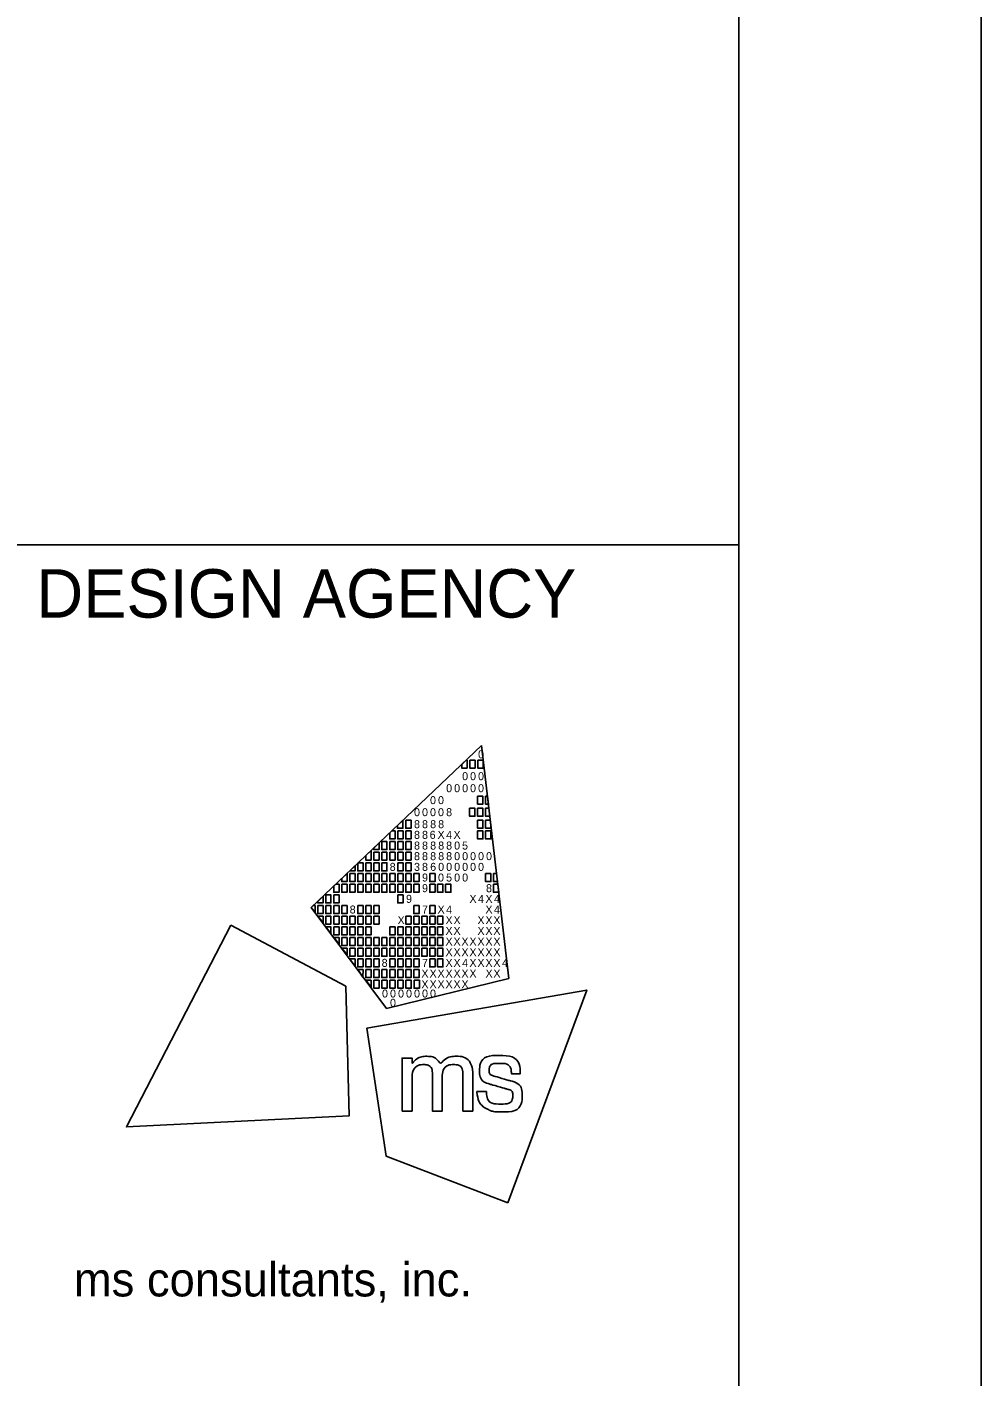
# Model space of a CAD drawing. Extents: x -5.3 to 69.2, y -33.8 to 22.
# Drawn here: x 32.03 to 34, y 2.785 to 5.569 of the extents above; entities that cross this region are included whole.
import ezdxf

# ---------------------------------------------------------------- set-up
doc = ezdxf.new("R2010")
doc.units = 0
for name, color, linetype in [('Default', 7, 'Continuous'), ('SH_Border', 7, 'Continuous'), ('SH_Cut_Line', 7, 'Continuous'), ('SH_Data', 7, 'Continuous')]:
    doc.layers.add(name, color=color, linetype=linetype)

msp = doc.modelspace()

# ---------------------------------------------------------------- linework, layer by layer
at = {"layer": 'Default'}
for p, q in [((32.6175, 3.7519), (32.9688, 4.0861)), ((32.9688, 4.0861), (32.9688, 4.0861)), ((32.9688, 4.0861), (33.0253, 3.6052)), ((32.773, 3.543), (32.6175, 3.7519)), ((33.0253, 3.6052), (32.773, 3.543))]:
    msp.add_line(p, q, dxfattribs=at)
for points in [[(32.9279, 4.0472), (32.9369, 4.0558), (32.9389, 4.0558), (32.9389, 4.0393), (32.9279, 4.0393)], [(32.9444, 4.0558), (32.9554, 4.0558), (32.9554, 4.0393), (32.9444, 4.0393)], [(32.9609, 4.0558), (32.9719, 4.0558), (32.9719, 4.0393), (32.9609, 4.0393)], [(32.9441, 3.9567), (32.9551, 3.9567), (32.9551, 3.9402), (32.9441, 3.9402)], [(32.9606, 3.9815), (32.9716, 3.9815), (32.9716, 3.965), (32.9606, 3.965)], [(32.9606, 3.9567), (32.9716, 3.9567), (32.9716, 3.9402), (32.9606, 3.9402)], [(32.9771, 3.9815), (32.9811, 3.9815), (32.983, 3.965), (32.9771, 3.965)], [(32.9771, 3.9567), (32.984, 3.9567), (32.9859, 3.9402), (32.9771, 3.9402)], [(32.7953, 3.9211), (32.8064, 3.9316), (32.8064, 3.9154), (32.7953, 3.9154)], [(32.8123, 3.9319), (32.8233, 3.9319), (32.8233, 3.9154), (32.8123, 3.9154)], [(32.9606, 3.9319), (32.9716, 3.9319), (32.9716, 3.9154), (32.9606, 3.9154)], [(32.9771, 3.9319), (32.9869, 3.9319), (32.9881, 3.9218), (32.9881, 3.9154), (32.9771, 3.9154)], [(32.7958, 3.9099), (32.8068, 3.9099), (32.8068, 3.8934), (32.7958, 3.8934)], [(32.8123, 3.9099), (32.8233, 3.9099), (32.8233, 3.8934), (32.8123, 3.8934)], [(32.9606, 3.9099), (32.9716, 3.9099), (32.9716, 3.8934), (32.9606, 3.8934)], [(32.9771, 3.9099), (32.9881, 3.9099), (32.9881, 3.8934), (32.9771, 3.8934)], [(32.7627, 3.8879), (32.7737, 3.8879), (32.7737, 3.8714), (32.7627, 3.8714)], [(32.7793, 3.8879), (32.7903, 3.8879), (32.7903, 3.8714), (32.7793, 3.8714)], [(32.7958, 3.8879), (32.8068, 3.8879), (32.8068, 3.8714), (32.7958, 3.8714)], [(32.8123, 3.8879), (32.8233, 3.8879), (32.8233, 3.8714), (32.8123, 3.8714)], [(32.7297, 3.8439), (32.7407, 3.8439), (32.7407, 3.8273), (32.7297, 3.8273)], [(32.7462, 3.8659), (32.7572, 3.8659), (32.7572, 3.8494), (32.7462, 3.8494)], [(32.7462, 3.8439), (32.7572, 3.8439), (32.7572, 3.8273), (32.7462, 3.8273)], [(32.7627, 3.8659), (32.7737, 3.8659), (32.7737, 3.8494), (32.7627, 3.8494)], [(32.7627, 3.8439), (32.7737, 3.8439), (32.7737, 3.8273), (32.7627, 3.8273)], [(32.7793, 3.8659), (32.7903, 3.8659), (32.7903, 3.8494), (32.7793, 3.8494)], [(32.7958, 3.8659), (32.8068, 3.8659), (32.8068, 3.8494), (32.7958, 3.8494)], [(32.7958, 3.8439), (32.8068, 3.8439), (32.8068, 3.8273), (32.7958, 3.8273)], [(32.8123, 3.8659), (32.8233, 3.8659), (32.8233, 3.8494), (32.8123, 3.8494)], [(32.8123, 3.8439), (32.8233, 3.8439), (32.8233, 3.8273), (32.8123, 3.8273)], [(32.6967, 3.8218), (32.7077, 3.8218), (32.7077, 3.8053), (32.6967, 3.8053)], [(32.7132, 3.8218), (32.7242, 3.8218), (32.7242, 3.8053), (32.7132, 3.8053)], [(32.7297, 3.8218), (32.7407, 3.8218), (32.7407, 3.8053), (32.7297, 3.8053)], [(32.7462, 3.8218), (32.7572, 3.8218), (32.7572, 3.8053), (32.7462, 3.8053)], [(32.7627, 3.8218), (32.7737, 3.8218), (32.7737, 3.8053), (32.7627, 3.8053)], [(32.7793, 3.8218), (32.7903, 3.8218), (32.7903, 3.8053), (32.7793, 3.8053)], [(32.7958, 3.8218), (32.8068, 3.8218), (32.8068, 3.8053), (32.7958, 3.8053)], [(32.8123, 3.8218), (32.8233, 3.8218), (32.8233, 3.8053), (32.8123, 3.8053)], [(32.8288, 3.8218), (32.8398, 3.8218), (32.8398, 3.8053), (32.8288, 3.8053)], [(32.8618, 3.8218), (32.8728, 3.8218), (32.8728, 3.8053), (32.8618, 3.8053)], [(32.9771, 3.8218), (32.9881, 3.8218), (32.9881, 3.8053), (32.9771, 3.8053)], [(32.9935, 3.8218), (32.9998, 3.8218), (33.0018, 3.8053), (32.9935, 3.8053)], [(32.6802, 3.7998), (32.6912, 3.7998), (32.6912, 3.7833), (32.6802, 3.7833)], [(32.6967, 3.7998), (32.7077, 3.7998), (32.7077, 3.7833), (32.6967, 3.7833)], [(32.7132, 3.7998), (32.7242, 3.7998), (32.7242, 3.7833), (32.7132, 3.7833)], [(32.7297, 3.7998), (32.7407, 3.7998), (32.7407, 3.7833), (32.7297, 3.7833)], [(32.7462, 3.7998), (32.7572, 3.7998), (32.7572, 3.7833), (32.7462, 3.7833)], [(32.7627, 3.7998), (32.7737, 3.7998), (32.7737, 3.7833), (32.7627, 3.7833)], [(32.7793, 3.7998), (32.7903, 3.7998), (32.7903, 3.7833), (32.7793, 3.7833)], [(32.7958, 3.7998), (32.8068, 3.7998), (32.8068, 3.7833), (32.7958, 3.7833)], [(32.8123, 3.7998), (32.8233, 3.7998), (32.8233, 3.7833), (32.8123, 3.7833)], [(32.8288, 3.7998), (32.8398, 3.7998), (32.8398, 3.7833), (32.8288, 3.7833)], [(32.8618, 3.7998), (32.8728, 3.7998), (32.8728, 3.7833), (32.8618, 3.7833)], [(32.8783, 3.7998), (32.8893, 3.7998), (32.8893, 3.7833), (32.8783, 3.7833)], [(32.8947, 3.7998), (32.9057, 3.7998), (32.9057, 3.7833), (32.8947, 3.7833)], [(32.9935, 3.7998), (33.0024, 3.7998), (33.0044, 3.7833), (32.9935, 3.7833)], [(32.6471, 3.7778), (32.6581, 3.7778), (32.6581, 3.7613), (32.6471, 3.7613)], [(32.6637, 3.7778), (32.6747, 3.7778), (32.6747, 3.7613), (32.6637, 3.7613)], [(32.7958, 3.7778), (32.8068, 3.7778), (32.8068, 3.7613), (32.7958, 3.7613)], [(32.6306, 3.7558), (32.6416, 3.7558), (32.6416, 3.7393), (32.6306, 3.7393)], [(32.6306, 3.7338), (32.6416, 3.7338), (32.6416, 3.72)], [(32.6471, 3.7558), (32.6581, 3.7558), (32.6581, 3.7393), (32.6471, 3.7393)], [(32.6471, 3.7338), (32.6581, 3.7338), (32.6581, 3.7173), (32.6471, 3.7173)], [(32.6637, 3.7558), (32.6747, 3.7558), (32.6747, 3.7393), (32.6637, 3.7393)], [(32.6637, 3.7338), (32.6747, 3.7338), (32.6747, 3.7173), (32.6637, 3.7173)], [(32.6802, 3.7558), (32.6912, 3.7558), (32.6912, 3.7393), (32.6802, 3.7393)], [(32.6802, 3.7338), (32.6912, 3.7338), (32.6912, 3.7173), (32.6802, 3.7173)], [(32.6967, 3.7338), (32.7077, 3.7338), (32.7077, 3.7173), (32.6967, 3.7173)], [(32.7132, 3.7558), (32.7242, 3.7558), (32.7242, 3.7393), (32.7132, 3.7393)], [(32.7132, 3.7338), (32.7242, 3.7338), (32.7242, 3.7173), (32.7132, 3.7173)], [(32.7297, 3.7558), (32.7407, 3.7558), (32.7407, 3.7393), (32.7297, 3.7393)], [(32.7297, 3.7338), (32.7407, 3.7338), (32.7407, 3.7173), (32.7297, 3.7173)], [(32.7462, 3.7558), (32.7572, 3.7558), (32.7572, 3.7393), (32.7462, 3.7393)], [(32.7462, 3.7338), (32.7572, 3.7338), (32.7572, 3.7173), (32.7462, 3.7173)], [(32.8123, 3.7338), (32.8233, 3.7338), (32.8233, 3.7173), (32.8123, 3.7173)], [(32.8288, 3.7558), (32.8398, 3.7558), (32.8398, 3.7393), (32.8288, 3.7393)], [(32.8288, 3.7338), (32.8398, 3.7338), (32.8398, 3.7173), (32.8288, 3.7173)], [(32.8453, 3.7338), (32.8563, 3.7338), (32.8563, 3.7173), (32.8453, 3.7173)], [(32.8618, 3.7558), (32.8728, 3.7558), (32.8728, 3.7393), (32.8618, 3.7393)], [(32.8618, 3.7338), (32.8728, 3.7338), (32.8728, 3.7173), (32.8618, 3.7173)], [(32.8783, 3.7338), (32.8893, 3.7338), (32.8893, 3.7173), (32.8783, 3.7173)], [(32.6471, 3.7117), (32.6581, 3.7117), (32.6581, 3.698)], [(32.6637, 3.7117), (32.6747, 3.7117), (32.6747, 3.6952), (32.6637, 3.6952)], [(32.6802, 3.7117), (32.6912, 3.7117), (32.6912, 3.6952), (32.6802, 3.6952)], [(32.6967, 3.7117), (32.7077, 3.7117), (32.7077, 3.6952), (32.6967, 3.6952)], [(32.7132, 3.7117), (32.7242, 3.7117), (32.7242, 3.6952), (32.7132, 3.6952)], [(32.7297, 3.7117), (32.7407, 3.7117), (32.7407, 3.6952), (32.7297, 3.6952)], [(32.7793, 3.7117), (32.7903, 3.7117), (32.7903, 3.6952), (32.7793, 3.6952)], [(32.7958, 3.7117), (32.8068, 3.7117), (32.8068, 3.6952), (32.7958, 3.6952)], [(32.8123, 3.7117), (32.8233, 3.7117), (32.8233, 3.6952), (32.8123, 3.6952)], [(32.8288, 3.7117), (32.8398, 3.7117), (32.8398, 3.6952), (32.8288, 3.6952)], [(32.8453, 3.7117), (32.8563, 3.7117), (32.8563, 3.6952), (32.8453, 3.6952)], [(32.8618, 3.7117), (32.8728, 3.7117), (32.8728, 3.6952), (32.8618, 3.6952)], [(32.8783, 3.7117), (32.8893, 3.7117), (32.8893, 3.6952), (32.8783, 3.6952)], [(32.6637, 3.6897), (32.6747, 3.6897), (32.6747, 3.676)], [(32.6747, 3.6897), (32.6747, 3.6897), (32.6747, 3.6897)], [(32.6802, 3.6897), (32.6912, 3.6897), (32.6912, 3.6732), (32.6802, 3.6732)], [(32.6967, 3.6897), (32.7077, 3.6897), (32.7077, 3.6732), (32.6967, 3.6732)], [(32.7132, 3.6897), (32.7242, 3.6897), (32.7242, 3.6732), (32.7132, 3.6732)], [(32.7297, 3.6897), (32.7407, 3.6897), (32.7407, 3.6732), (32.7297, 3.6732)], [(32.7462, 3.6897), (32.7572, 3.6897), (32.7572, 3.6732), (32.7462, 3.6732)], [(32.7627, 3.6897), (32.7737, 3.6897), (32.7737, 3.6732), (32.7627, 3.6732)], [(32.7793, 3.6897), (32.7903, 3.6897), (32.7903, 3.6732), (32.7793, 3.6732)], [(32.7958, 3.6897), (32.8068, 3.6897), (32.8068, 3.6732), (32.7958, 3.6732)], [(32.8123, 3.6897), (32.8233, 3.6897), (32.8233, 3.6732), (32.8123, 3.6732)], [(32.8288, 3.6897), (32.8398, 3.6897), (32.8398, 3.6732), (32.8288, 3.6732)], [(32.8453, 3.6897), (32.8563, 3.6897), (32.8563, 3.6732), (32.8453, 3.6732)], [(32.8618, 3.6897), (32.8728, 3.6897), (32.8728, 3.6732), (32.8618, 3.6732)], [(32.8783, 3.6897), (32.8893, 3.6897), (32.8893, 3.6732), (32.8783, 3.6732)], [(32.6802, 3.6677), (32.6912, 3.6677), (32.6912, 3.654)], [(32.6967, 3.6677), (32.7077, 3.6677), (32.7077, 3.6512), (32.6967, 3.6512)], [(32.7132, 3.6677), (32.7242, 3.6677), (32.7242, 3.6512), (32.7132, 3.6512)], [(32.7297, 3.6677), (32.7407, 3.6677), (32.7407, 3.6512), (32.7297, 3.6512)], [(32.7462, 3.6677), (32.7572, 3.6677), (32.7572, 3.6512), (32.7462, 3.6512)], [(32.7627, 3.6677), (32.7737, 3.6677), (32.7737, 3.6512), (32.7627, 3.6512)], [(32.7793, 3.6677), (32.7903, 3.6677), (32.7903, 3.6512), (32.7793, 3.6512)], [(32.7958, 3.6677), (32.8068, 3.6677), (32.8068, 3.6512), (32.7958, 3.6512)], [(32.8123, 3.6677), (32.8233, 3.6677), (32.8233, 3.6512), (32.8123, 3.6512)], [(32.8288, 3.6677), (32.8398, 3.6677), (32.8398, 3.6512), (32.8288, 3.6512)], [(32.8453, 3.6677), (32.8563, 3.6677), (32.8563, 3.6512), (32.8453, 3.6512)], [(32.8618, 3.6677), (32.8728, 3.6677), (32.8728, 3.6512), (32.8618, 3.6512)], [(32.8783, 3.6677), (32.8893, 3.6677), (32.8893, 3.6512), (32.8783, 3.6512)], [(32.7077, 3.6305), (32.6965, 3.6457), (32.7077, 3.6457)], [(32.7132, 3.6457), (32.7242, 3.6457), (32.7242, 3.6292), (32.7132, 3.6292)], [(32.724, 3.6082), (32.7132, 3.6237), (32.7242, 3.6237)], [(32.7297, 3.6457), (32.7407, 3.6457), (32.7407, 3.6292), (32.7297, 3.6292)], [(32.7297, 3.6237), (32.7407, 3.6237), (32.7407, 3.6072), (32.7297, 3.6072)], [(32.7462, 3.6457), (32.7572, 3.6457), (32.7572, 3.6292), (32.7462, 3.6292)], [(32.7462, 3.6237), (32.7572, 3.6237), (32.7572, 3.6072), (32.7462, 3.6072)], [(32.7627, 3.6237), (32.7737, 3.6237), (32.7737, 3.6072), (32.7627, 3.6072)], [(32.7793, 3.6457), (32.7903, 3.6457), (32.7903, 3.6292), (32.7793, 3.6292)], [(32.7793, 3.6237), (32.7903, 3.6237), (32.7903, 3.6072), (32.7793, 3.6072)], [(32.7958, 3.6457), (32.8068, 3.6457), (32.8068, 3.6292), (32.7958, 3.6292)], [(32.7958, 3.6237), (32.8068, 3.6237), (32.8068, 3.6072), (32.7958, 3.6072)], [(32.8123, 3.6457), (32.8233, 3.6457), (32.8233, 3.6292), (32.8123, 3.6292)], [(32.8123, 3.6237), (32.8233, 3.6237), (32.8233, 3.6072), (32.8123, 3.6072)], [(32.8288, 3.6457), (32.8398, 3.6457), (32.8398, 3.6292), (32.8288, 3.6292)], [(32.8288, 3.6237), (32.8398, 3.6237), (32.8398, 3.6072), (32.8288, 3.6072)], [(32.8618, 3.6457), (32.8728, 3.6457), (32.8728, 3.6292), (32.8618, 3.6292)], [(32.8783, 3.6457), (32.8893, 3.6457), (32.8893, 3.6292), (32.8783, 3.6292)], [(32.7302, 3.6017), (32.7407, 3.6017), (32.7408, 3.5875)], [(32.7463, 3.6017), (32.7573, 3.6017), (32.7573, 3.5852), (32.7463, 3.5852)], [(32.763, 3.6017), (32.774, 3.6017), (32.774, 3.5852), (32.763, 3.5852)], [(32.7794, 3.6017), (32.7904, 3.6017), (32.7904, 3.5852), (32.7794, 3.5852)], [(32.796, 3.6017), (32.807, 3.6017), (32.807, 3.5852), (32.796, 3.5852)], [(32.8129, 3.6017), (32.8239, 3.6017), (32.8239, 3.5851), (32.8129, 3.5851)], [(32.8296, 3.6017), (32.8406, 3.6017), (32.8406, 3.5851), (32.8296, 3.5851)]]:
    msp.add_lwpolyline(points, close=True, dxfattribs=at)
for points in [[(32.7903, 3.9099), (32.7836, 3.9099), (32.7793, 3.9058), (32.7793, 3.8934), (32.7903, 3.8934), (32.7903, 3.9099)], [(32.7572, 3.8849), (32.7462, 3.8744), (32.7462, 3.8714), (32.7572, 3.8714), (32.7572, 3.8849)], [(32.7242, 3.8439), (32.7141, 3.8439), (32.7132, 3.843), (32.7132, 3.8273), (32.7242, 3.8273), (32.7242, 3.8439)], [(32.7407, 3.8691), (32.7297, 3.8587), (32.7297, 3.8494), (32.7407, 3.8494), (32.7407, 3.8691)], [(32.6912, 3.822), (32.6802, 3.8115), (32.6802, 3.8053), (32.6912, 3.8053), (32.6912, 3.822)], [(32.7077, 3.8377), (32.6968, 3.8273), (32.7077, 3.8273), (32.7077, 3.8377)], [(32.6747, 3.7998), (32.6679, 3.7998), (32.6637, 3.7958), (32.6637, 3.7833), (32.6747, 3.7833), (32.6747, 3.7998)], [(32.6416, 3.7749), (32.6306, 3.7644), (32.6306, 3.7613), (32.6416, 3.7613), (32.6416, 3.7749)], [(32.6251, 3.7558), (32.6216, 3.7558), (32.6175, 3.7519), (32.6251, 3.7417), (32.6251, 3.7558)], [(32.4512, 3.7149), (32.2359, 3.2988), (32.6956, 3.3215), (32.6884, 3.5892), (32.4512, 3.7149)], [(33.0229, 3.1422), (33.1859, 3.5814), (32.7324, 3.5029), (32.7722, 3.2381), (33.0229, 3.1422)]]:
    msp.add_lwpolyline(points, dxfattribs=at)
for points in [[(32.8048, 3.3315), (32.8048, 3.3315), (32.8048, 3.4409), (32.8048, 3.4409), (32.8048, 3.4409), (32.8255, 3.4409), (32.8255, 3.4409), (32.8255, 3.4409), (32.8255, 3.4297), (32.8255, 3.4297), (32.8346, 3.4399), (32.8457, 3.4445), (32.8555, 3.4445), (32.8688, 3.4445), (32.8791, 3.4372), (32.8837, 3.4266), (32.8915, 3.4381), (32.905, 3.4446), (32.9166, 3.4446), (32.9325, 3.4446), (32.9451, 3.435), (32.9494, 3.4213), (32.9494, 3.4212), (32.9494, 3.4212), (32.9494, 3.4212), (32.9501, 3.419), (32.9506, 3.4172), (32.9506, 3.4071), (32.9506, 3.4071), (32.9506, 3.3314), (32.9506, 3.3314), (32.9506, 3.3314), (32.9303, 3.3314), (32.9303, 3.3314), (32.9303, 3.3314), (32.9303, 3.4048), (32.9303, 3.4048), (32.9303, 3.4201), (32.9219, 3.4274), (32.911, 3.4274), (32.8995, 3.4274), (32.8879, 3.4171), (32.8879, 3.4001), (32.8879, 3.4001), (32.8879, 3.3315), (32.8879, 3.3315), (32.8879, 3.3315), (32.8674, 3.3315), (32.8674, 3.3315), (32.8674, 3.3315), (32.8674, 3.4059), (32.8674, 3.4059), (32.8674, 3.4203), (32.8588, 3.4274), (32.8496, 3.4274), (32.8384, 3.4274), (32.8254, 3.417), (32.8254, 3.3962), (32.8254, 3.3962), (32.8254, 3.3315), (32.8254, 3.3315), (32.8254, 3.3315), (32.8048, 3.3315), (32.8048, 3.3315)], [(32.9595, 3.3709), (32.9595, 3.3709), (32.9595, 3.3717), (32.9595, 3.3717), (32.9595, 3.3717), (32.9603, 3.3717), (32.9603, 3.3717), (32.9603, 3.3717), (32.9783, 3.3717), (32.9783, 3.3717), (32.9783, 3.3717), (32.9789, 3.3717), (32.9789, 3.3717), (32.9789, 3.3717), (32.979, 3.371), (32.979, 3.371), (32.9803, 3.3554), (32.9887, 3.346), (33.009, 3.346), (33.0273, 3.346), (33.0333, 3.3554), (33.0333, 3.3631), (33.0333, 3.3732), (33.0256, 3.3758), (33.0175, 3.378), (33.0175, 3.378), (32.987, 3.3867), (32.987, 3.3867), (32.972, 3.3909), (32.9648, 3.4019), (32.9648, 3.4142), (32.9648, 3.4303), (32.9768, 3.4462), (33.0052, 3.4462), (33.0348, 3.4462), (33.0489, 3.4285), (33.0489, 3.4095), (33.0489, 3.4095), (33.0489, 3.4087), (33.0489, 3.4087), (33.0489, 3.4087), (33.0482, 3.4087), (33.0482, 3.4087), (33.0482, 3.4087), (33.0312, 3.4087), (33.0312, 3.4087), (33.0312, 3.4087), (33.0305, 3.4087), (33.0305, 3.4087), (33.0305, 3.4087), (33.0305, 3.4094), (33.0305, 3.4094), (33.0301, 3.4208), (33.0226, 3.43), (33.0056, 3.43), (32.9891, 3.43), (32.9843, 3.4218), (32.9843, 3.4157), (32.9843, 3.4108), (32.9869, 3.4059), (32.9959, 3.4033), (32.9959, 3.4033), (33.0255, 3.3948), (33.0255, 3.3948), (33.0462, 3.3889), (33.0527, 3.3777), (33.0527, 3.3639), (33.0527, 3.3462), (33.041, 3.3298), (33.0087, 3.3298), (32.9952, 3.3298), (32.9877, 3.3321), (32.9823, 3.3348), (32.969, 3.3414), (32.9609, 3.3536), (32.9595, 3.3709)]]:
    msp.add_open_spline(points, degree=3, dxfattribs=at)
at = {"layer": 'SH_Border'}
msp.add_line((32, 4.5), (33.5, 4.5), dxfattribs=at)
msp.add_lwpolyline([(1.5, 21.5), (33.5, 21.5), (33.5, 0.5), (1.5, 0.5)], close=True, dxfattribs=at)
at = {"layer": 'SH_Cut_Line'}
msp.add_lwpolyline([(0, 0), (34, 0), (34, 22), (0, 22)], close=True, dxfattribs=at)
at = {"layer": 'SH_Data'}
msp.add_line((32.75, 3.5), (32.75, 3.5), dxfattribs=at)

# ---------------------------------------------------------------- texts
at = {"layer": 'Default'}
for s, p in [('0', (32.9617, 4.0597)), ('0', (32.9288, 4.0145)), ('0', (32.9452, 4.0145)), ('0', (32.9617, 4.0145)), ('0', (32.8958, 3.9897)), ('0', (32.9123, 3.9897)), ('0', (32.9288, 3.9897)), ('0', (32.9452, 3.9897)), ('0', (32.9617, 3.9897)), ('0', (32.8295, 3.9402)), ('0', (32.846, 3.9402)), ('0', (32.8625, 3.965)), ('0', (32.8625, 3.9402)), ('0', (32.879, 3.965)), ('0', (32.879, 3.9402)), ('8', (32.8958, 3.9402)), ('8', (32.8295, 3.9154)), ('8', (32.846, 3.9154)), ('8', (32.8628, 3.9154)), ('8', (32.8793, 3.9154)), ('8', (32.8295, 3.8934)), ('8', (32.846, 3.8934)), ('6', (32.8618, 3.8934)), ('X', (32.8781, 3.8934)), ('4', (32.8958, 3.8934)), ('X', (32.911, 3.8934)), ('8', (32.8295, 3.8713)), ('8', (32.846, 3.8713)), ('8', (32.8628, 3.8713)), ('8', (32.8794, 3.8713)), ('8', (32.8958, 3.8713)), ('0', (32.9123, 3.8713)), ('5', (32.9287, 3.8713)), ('8', (32.7793, 3.8273)), ('3', (32.8295, 3.8273)), ('8', (32.8295, 3.8494)), ('8', (32.846, 3.8494)), ('8', (32.846, 3.8273)), ('8', (32.8628, 3.8494)), ('6', (32.8629, 3.8273)), ('0', (32.8793, 3.8273)), ('8', (32.8794, 3.8494)), ('8', (32.8958, 3.8494)), ('0', (32.8958, 3.8273)), ('0', (32.9123, 3.8494)), ('0', (32.9123, 3.8273)), ('0', (32.9288, 3.8494)), ('0', (32.9288, 3.8273)), ('0', (32.9452, 3.8494)), ('0', (32.9452, 3.8273)), ('0', (32.9617, 3.8494)), ('0', (32.9617, 3.8273)), ('0', (32.9782, 3.8494)), ('9', (32.846, 3.8053)), ('0', (32.879, 3.8053)), ('5', (32.8957, 3.8053)), ('0', (32.9123, 3.8053)), ('0', (32.9288, 3.8053)), ('9', (32.846, 3.7833)), ('8', (32.9781, 3.7833)), ('9', (32.813, 3.7613)), ('X', (32.9439, 3.7613)), ('4', (32.9617, 3.7613)), ('X', (32.9769, 3.7613)), ('4', (32.9946, 3.7613)), ('8', (32.6967, 3.7393)), ('X', (32.7955, 3.7173)), ('7', (32.846, 3.7393)), ('X', (32.8781, 3.7393)), ('X', (32.8945, 3.7173)), ('4', (32.8958, 3.7393)), ('X', (32.911, 3.7173)), ('X', (32.9604, 3.7173)), ('X', (32.9769, 3.7393)), ('X', (32.9769, 3.7173)), ('X', (32.9933, 3.7173)), ('4', (32.9946, 3.7393)), ('X', (32.8945, 3.6952)), ('X', (32.911, 3.6952)), ('X', (32.9604, 3.6952)), ('X', (32.9769, 3.6952)), ('X', (32.9933, 3.6952)), ('X', (32.8945, 3.6732)), ('X', (32.911, 3.6732)), ('X', (32.9274, 3.6732)), ('X', (32.9439, 3.6732)), ('X', (32.9604, 3.6732)), ('X', (32.9769, 3.6732)), ('X', (32.9933, 3.6732)), ('X', (32.8945, 3.6512)), ('X', (32.911, 3.6512)), ('X', (32.9274, 3.6512)), ('X', (32.9439, 3.6512)), ('X', (32.9604, 3.6512)), ('X', (32.9769, 3.6512)), ('X', (32.9933, 3.6512)), ('8', (32.7627, 3.6292)), ('X', (32.8447, 3.6072)), ('7', (32.846, 3.6292)), ('X', (32.8616, 3.6072)), ('X', (32.878, 3.6072)), ('X', (32.8945, 3.6292)), ('X', (32.8945, 3.6072)), ('X', (32.911, 3.6292)), ('X', (32.911, 3.6072)), ('X', (32.9274, 3.6072)), ('4', (32.9288, 3.6292)), ('X', (32.9439, 3.6292)), ('X', (32.9439, 3.6072)), ('X', (32.9604, 3.6292)), ('X', (32.9769, 3.6292)), ('X', (32.9771, 3.6072)), ('X', (32.9933, 3.6292)), ('X', (32.9933, 3.6072)), ('4', (33.0111, 3.6292)), ('X', (32.8447, 3.5851)), ('X', (32.8616, 3.5851)), ('X', (32.878, 3.5851)), ('X', (32.8945, 3.5851)), ('X', (32.911, 3.5851)), ('X', (32.9274, 3.5851)), ('0', (32.7634, 3.5659)), ('0', (32.7799, 3.5659)), ('0', (32.7965, 3.5659)), ('0', (32.813, 3.5659)), ('0', (32.8295, 3.5659)), ('0', (32.846, 3.5659)), ('0', (32.8625, 3.5659)), ('0', (32.7799, 3.5467))]:
    msp.add_text(s, height=0.0165, rotation=360, dxfattribs=at).set_placement(p)
at = {"layer": 'SH_Border'}
msp.add_text('ms consultants, inc.', height=0.07, rotation=360, dxfattribs=at).set_placement((32.1273, 2.9489))
at = {"layer": 'SH_Data'}
msp.add_text('DESIGN AGENCY', height=0.1, dxfattribs=at).set_placement((32.05, 4.35))

doc.saveas('drawing.dxf')
